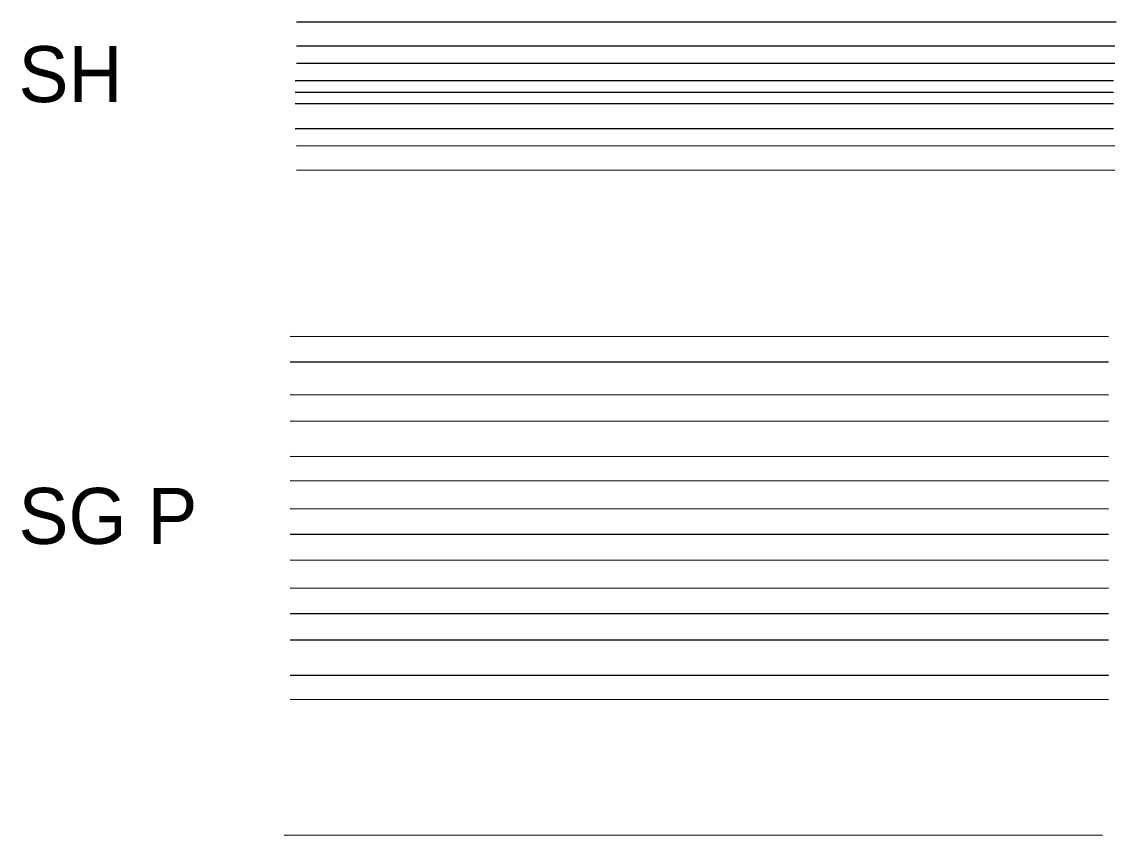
# Model space of a CAD drawing. Extents: x 19437 to 1370217, y 6871 to 405972.
# Drawn here: x 21222 to 22396, y 12090 to 12962 of the extents above; entities that cross this region are included whole.
import ezdxf

# ---------------------------------------------------------------- set-up
doc = ezdxf.new("R2010")
doc.units = 0
for name, color, linetype in [('Default', 7, 'Continuous'), ('SG_P_Conc_Work_Pad', 7, 'Continuous'), ('SG_P_Conduit', 7, 'Continuous'), ('SG_P_Controllers', 7, 'Continuous'), ('SG_P_Detection', 7, 'Continuous'), ('SG_P_Foundation', 7, 'Continuous'), ('SG_P_Heads', 7, 'Continuous'), ('SG_P_Interconnect_Cable', 7, 'Continuous'), ('SG_P_Manhole', 7, 'Continuous'), ('SG_P_Mast_Arm', 7, 'Continuous'), ('SG_P_Messenger_Wire', 7, 'Continuous'), ('SG_P_Poles', 7, 'Continuous'), ('SG_P_PullBox', 7, 'Continuous'), ('SG_P_Text', 7, 'Continuous'), ('SG_P_Wiring', 7, 'Continuous'), ('SG_X_Conc_Work_Pad', 7, 'Continuous'), ('SH_Border', 7, 'Continuous'), ('SH_Cut_Line', 7, 'Continuous'), ('SH_Cut_Line2', 7, 'Continuous'), ('SH_Data', 7, 'Continuous'), ('SH_Major_Grid_Line', 7, 'Continuous'), ('SH_Masking', 7, 'Continuous'), ('SH_Minor_Grid_Line', 7, 'Continuous'), ('SH_Named_Boundary', 7, 'Continuous'), ('SH_Text', 7, 'Continuous')]:
    doc.layers.add(name, color=color, linetype=linetype)

msp = doc.modelspace()

# ---------------------------------------------------------------- linework, layer by layer
at = {"layer": 'SG_P_Conc_Work_Pad'}
msp.add_lwpolyline([(21510.2, 12624.7), (21510.2, 12624.7), (22387.5, 12624.5), (22387.5, 12624.5)], dxfattribs=at)
at = {"layer": 'SG_P_Conduit'}
msp.add_lwpolyline([(21510.2, 12597.4), (21510.2, 12597.4), (22387.5, 12597.2), (22387.5, 12597.2)], dxfattribs=at)
at = {"layer": 'SG_P_Controllers'}
msp.add_lwpolyline([(21510.2, 12562.2), (21510.2, 12562.2), (22387.5, 12562), (22387.5, 12562)], dxfattribs=at)
at = {"layer": 'SG_P_Detection'}
msp.add_lwpolyline([(21510.2, 12534), (21510.2, 12534), (22387.5, 12533.8), (22387.5, 12533.8)], dxfattribs=at)
at = {"layer": 'SG_P_Foundation'}
msp.add_lwpolyline([(21510.2, 12496.2), (21510.2, 12496.2), (22387.5, 12496), (22387.5, 12496)], dxfattribs=at)
at = {"layer": 'SG_P_Heads'}
msp.add_lwpolyline([(21510.2, 12470.1), (21510.2, 12470.1), (22387.5, 12469.9), (22387.5, 12469.9)], dxfattribs=at)
at = {"layer": 'SG_P_Interconnect_Cable'}
msp.add_lwpolyline([(21510.2, 12440.1), (21510.2, 12440.1), (22387.5, 12439.9), (22387.5, 12439.9)], dxfattribs=at)
at = {"layer": 'SG_P_Manhole'}
msp.add_lwpolyline([(21510.2, 12412.8), (21510.2, 12412.8), (22387.5, 12412.6), (22387.5, 12412.6)], dxfattribs=at)
at = {"layer": 'SG_P_Mast_Arm'}
msp.add_lwpolyline([(21510.2, 12385.1), (21510.2, 12385.1), (22387.5, 12384.9), (22387.5, 12384.9)], dxfattribs=at)
at = {"layer": 'SG_P_Messenger_Wire'}
msp.add_lwpolyline([(21510.2, 12355.1), (21510.2, 12355.1), (22387.5, 12354.9), (22387.5, 12354.9)], dxfattribs=at)
at = {"layer": 'SG_P_Poles'}
msp.add_lwpolyline([(21510.2, 12327.8), (21510.2, 12327.8), (22387.5, 12327.6), (22387.5, 12327.6)], dxfattribs=at)
at = {"layer": 'SG_P_PullBox'}
msp.add_lwpolyline([(21510.2, 12299.5), (21510.2, 12299.5), (22387.5, 12299.3), (22387.5, 12299.3)], dxfattribs=at)
at = {"layer": 'SG_P_Text'}
msp.add_lwpolyline([(21510.2, 12261.7), (21510.2, 12261.7), (22387.5, 12261.5), (22387.5, 12261.5)], dxfattribs=at)
at = {"layer": 'SG_P_Wiring'}
msp.add_lwpolyline([(21510.2, 12235.7), (21510.2, 12235.7), (22387.5, 12235.4), (22387.5, 12235.4)], dxfattribs=at)
at = {"layer": 'SG_X_Conc_Work_Pad'}
msp.add_lwpolyline([(21503.6, 12090.4), (21503.6, 12090.4), (22380.9, 12090.2), (22380.9, 12090.2)], dxfattribs=at)
at = {"layer": 'SH_Border'}
msp.add_lwpolyline([(21516.8, 12961.6), (21516.8, 12961.6), (22395.5, 12961.6)], dxfattribs=at)
at = {"layer": 'SH_Cut_Line'}
msp.add_lwpolyline([(21516.8, 12935.8), (21516.8, 12935.8), (22394.1, 12935.8)], dxfattribs=at)
at = {"layer": 'SH_Cut_Line2'}
msp.add_lwpolyline([(21516.9, 12829), (21516.9, 12829), (22394.1, 12828.8), (22394.1, 12828.8)], dxfattribs=at)
at = {"layer": 'SH_Data'}
msp.add_line((21515.5, 12847.5), (22392.8, 12847.5), dxfattribs=at)
at = {"layer": 'SH_Major_Grid_Line'}
msp.add_line((21515.5, 12874.3), (22392.8, 12874.3), dxfattribs=at)
at = {"layer": 'SH_Masking'}
msp.add_line((21515.5, 12886.4), (22392.8, 12886.4), dxfattribs=at)
at = {"layer": 'SH_Minor_Grid_Line'}
msp.add_lwpolyline([(21516.9, 12802.9), (21516.9, 12802.9), (22394.1, 12802.7), (22394.1, 12802.7)], dxfattribs=at)
at = {"layer": 'SH_Named_Boundary'}
msp.add_lwpolyline([(21516.8, 12917.5), (21516.8, 12917.5), (22394.1, 12917.5)], dxfattribs=at)
at = {"layer": 'SH_Text'}
msp.add_line((21515.5, 12898.6), (22392.8, 12898.6), dxfattribs=at)

# ---------------------------------------------------------------- texts
at = {"layer": 'Default'}
msp.add_text('SG P', height=60, dxfattribs=at).set_placement((21218.8, 12402.2))
at = {"layer": 'SH_Text'}
msp.add_text('SH', height=60, dxfattribs=at).set_placement((21218.8, 12875.6))

doc.saveas('drawing.dxf')
